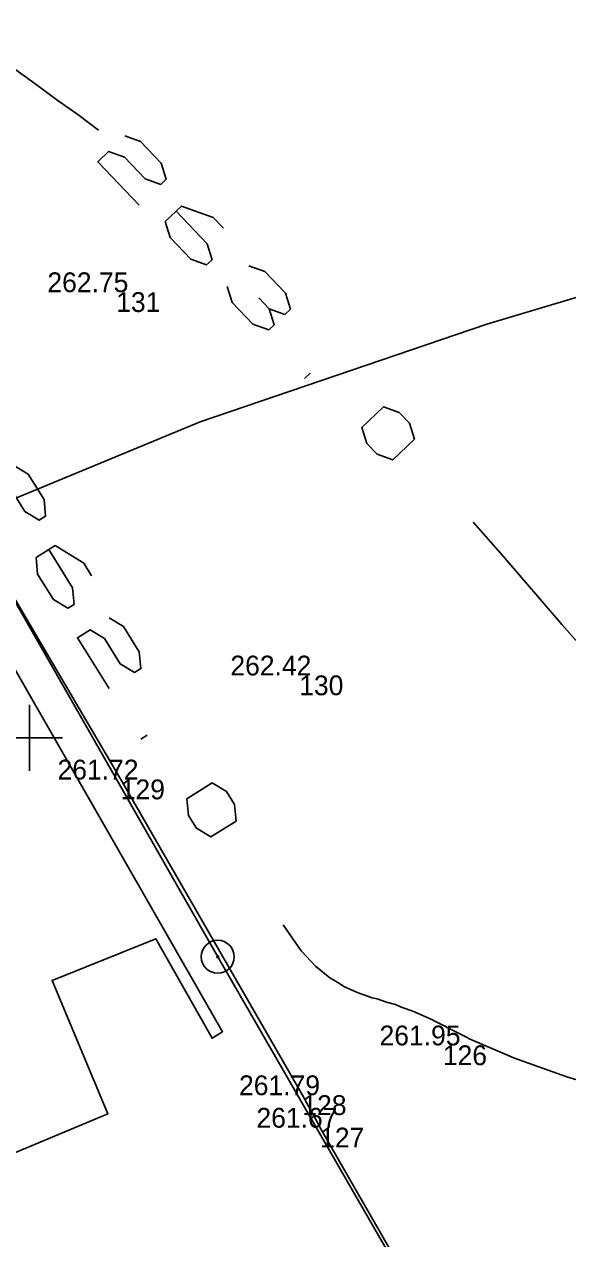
# Model space of a CAD drawing. Extents: x -771260 to -770828, y -1053564 to -1052811.
# Drawn here: x -771150.16 to -771133.69, y -1053315.19 to -1053278.38 of the extents above; entities that cross this region are included whole.
import ezdxf

# ---------------------------------------------------------------- set-up
doc = ezdxf.new("R2010")
doc.units = 0
for name, color, linetype in [('14_8_2023_krizky', 7, 'Continuous'), ('25_3_2019_krizky_JTSK', 7, 'Continuous'), ('25_3_2019_oploceni', 7, 'Continuous'), ('25_3_2019_vrstevnice_interval_po_1m', 7, 'Continuous'), ('25_3_2019_vstup_vjezd_pozemek', 7, 'Continuous'), ('25_3_2019_zamereny_bod', 7, 'Continuous'), ('25_3_2019_zamereny_bod_cislo', 7, 'Continuous'), ('25_3_2019_zamereny_bod_vyska', 7, 'Continuous'), ('Default', 7, 'Continuous'), ('DKM_Hranice parcel', 7, 'Continuous'), ('DKM_Značky bodu BP', 7, 'Continuous')]:
    doc.layers.add(name, color=color, linetype=linetype)

# ---------------------------------------------------------------- blocks, each defined once
blk = doc.blocks.new('POINT_DISPLAY')
at = {"layer": 'Default'}
blk.add_line((0, 0), (0, 0), dxfattribs=at)
blk = doc.blocks.new('KRIZEK')
at = {"layer": '25_3_2019_krizky_JTSK'}
for p, q in [((0, 10), (0, -10)), ((-10, 0), (10, 0))]:
    blk.add_line(p, q, dxfattribs=at)

msp = doc.modelspace()

# ---------------------------------------------------------------- linework, layer by layer
at = {"layer": '25_3_2019_oploceni'}
for p, q in [((-771147.237, -1053301.266), (-771151.821, -1053293.463)), ((-771141.735, -1053310.835), (-771147.238, -1053301.267)), ((-771134.779, -1053322.964), (-771141.196, -1053311.82))]:
    msp.add_line(p, q, dxfattribs=at)
at = {"layer": '25_3_2019_vrstevnice_interval_po_1m'}
for points in [[(-771153.199, -1053277.504), (-771152.035, -1053278.507), (-771151.999, -1053278.538), (-771151.054, -1053279.264), (-771150.533, -1053279.674), (-771149.799, -1053280.202), (-771149.134, -1053280.696), (-771148.539, -1053281.114), (-771147.912, -1053281.584)], [(-771149.799, -1053280.202), (-771149.799, -1053280.202)], [(-771149.134, -1053280.696), (-771149.134, -1053280.696)], [(-771148.539, -1053281.114), (-771148.539, -1053281.114)], [(-771147.114, -1053281.763), (-771146.636, -1053281.934), (-771146.009, -1053282.591), (-771145.86, -1053283.076), (-771146.024, -1053283.232), (-771146.501, -1053283.061), (-771147.128, -1053282.404), (-771147.606, -1053282.233), (-771147.934, -1053282.546), (-771146.68, -1053283.859)], [(-771145.561, -1053284.046), (-771144.621, -1053285.03), (-771144.471, -1053285.515), (-771144.636, -1053285.672), (-771145.113, -1053285.501), (-771145.74, -1053284.844), (-771145.889, -1053284.359), (-771145.397, -1053283.889), (-771144.442, -1053284.232), (-771144.128, -1053284.56)], [(-771143.352, -1053285.702), (-771142.875, -1053285.873), (-771142.248, -1053286.53), (-771142.098, -1053287.015), (-771142.263, -1053287.171), (-771142.74, -1053287)], [(-771142.74, -1053287), (-771142.591, -1053287.485), (-771142.755, -1053287.642), (-771143.232, -1053287.47), (-771143.859, -1053286.814), (-771144.009, -1053286.329)], [(-771142.74, -1053287), (-771143.054, -1053286.672)], [(-771141.665, -1053289.111), (-771141.501, -1053288.955)], [(-771139.785, -1053291.081), (-771139.934, -1053290.596), (-771139.277, -1053289.969), (-771138.8, -1053290.14), (-771138.486, -1053290.469), (-771138.337, -1053290.954), (-771138.994, -1053291.581), (-771139.471, -1053291.409), (-771139.785, -1053291.081)], [(-771150.477, -1053291.749), (-771150.044, -1053292.013), (-771149.563, -1053292.783), (-771149.515, -1053293.288), (-771149.708, -1053293.408), (-771150.141, -1053293.144), (-771150.622, -1053292.374), (-771151.055, -1053292.109), (-771151.44, -1053292.35), (-771150.477, -1053293.89)], [(-771136.561, -1053293.471), (-771136.561, -1053293.471)], [(-771136.561, -1053293.471), (-771136.552, -1053293.481), (-771135.648, -1053294.495), (-771133.861, -1053296.577), (-771133.233, -1053297.289)], [(-771149.419, -1053294.298), (-771148.697, -1053295.453), (-771148.649, -1053295.958), (-771148.842, -1053296.079), (-771149.275, -1053295.814), (-771149.756, -1053295.044), (-771149.804, -1053294.539), (-771149.227, -1053294.178), (-771148.361, -1053294.707), (-771148.12, -1053295.092)], [(-771135.648, -1053294.495), (-771135.648, -1053294.495)], [(-771147.591, -1053296.367), (-771147.158, -1053296.632), (-771146.677, -1053297.402), (-771146.629, -1053297.907), (-771146.821, -1053298.027), (-771147.254, -1053297.762), (-771147.735, -1053296.993), (-771148.168, -1053296.728), (-771148.553, -1053296.969), (-771147.591, -1053298.508)], [(-771133.861, -1053296.577), (-771133.861, -1053296.577)], [(-771146.629, -1053300.048), (-771146.436, -1053299.927)], [(-771145.186, -1053302.357), (-771145.234, -1053301.852), (-771144.464, -1053301.371), (-771144.031, -1053301.635), (-771143.79, -1053302.02), (-771143.742, -1053302.525), (-771144.512, -1053303.006), (-771144.945, -1053302.742), (-771145.186, -1053302.357)], [(-771142.312, -1053305.671), (-771142.312, -1053305.671)], [(-771142.312, -1053305.671), (-771141.768, -1053306.462), (-771141.762, -1053306.47), (-771141.332, -1053306.92), (-771140.903, -1053307.276), (-771140.614, -1053307.449), (-771140.474, -1053307.543), (-771140.046, -1053307.736), (-771139.618, -1053307.883), (-771139.466, -1053307.912), (-771139.19, -1053308.014), (-771138.915, -1053308.083), (-771138.762, -1053308.153), (-771138.334, -1053308.313), (-771137.774, -1053308.562), (-771137.758, -1053308.569), (-771136.965, -1053308.977), (-771136.725, -1053309.101), (-771136.697, -1053309.113), (-771135.303, -1053309.712), (-771133.721, -1053310.279), (-771133.087, -1053310.474)], [(-771141.762, -1053306.47), (-771141.762, -1053306.47)], [(-771141.332, -1053306.92), (-771141.332, -1053306.92)], [(-771140.903, -1053307.276), (-771140.903, -1053307.276)], [(-771140.614, -1053307.449), (-771140.614, -1053307.449)], [(-771140.474, -1053307.543), (-771140.474, -1053307.543)], [(-771140.046, -1053307.736), (-771140.046, -1053307.736)], [(-771139.618, -1053307.883), (-771139.618, -1053307.883)], [(-771139.466, -1053307.912), (-771139.466, -1053307.912)], [(-771139.19, -1053308.014), (-771139.19, -1053308.014)], [(-771138.915, -1053308.083), (-771138.915, -1053308.083)], [(-771138.762, -1053308.153), (-771138.762, -1053308.153)], [(-771138.334, -1053308.313), (-771138.334, -1053308.313)], [(-771137.758, -1053308.569), (-771137.758, -1053308.569)], [(-771136.725, -1053309.101), (-771136.725, -1053309.101)], [(-771135.303, -1053309.712), (-771135.303, -1053309.712)], [(-771133.721, -1053310.279), (-771133.721, -1053310.279)]]:
    msp.add_lwpolyline(points, dxfattribs=at)
at = {"layer": '25_3_2019_vstup_vjezd_pozemek'}
msp.add_line((-771141.734, -1053310.835), (-771141.196, -1053311.819), dxfattribs=at)
at = {"layer": 'DKM_Hranice parcel'}
for points in [[(-771151.89, -1053293.35), (-771144.83, -1053290.43), (-771136.15, -1053287.47), (-771127.19, -1053284.79), (-771125.28, -1053284.32)], [(-771134.86, -1053323.01), (-771144.3, -1053306.64), (-771151.89, -1053293.35)], [(-771154.06, -1053298.56), (-771153.54, -1053299.72), (-771150.56, -1053298.42), (-771151.17, -1053297.4), (-771150.85, -1053297.22), (-771144.15, -1053308.91), (-771144.47, -1053309.11), (-771146.17, -1053306.1), (-771149.32, -1053307.36), (-771147.63, -1053311.4), (-771152.05, -1053313.25), (-771152.83, -1053311.43), (-771157.76, -1053313.5), (-771160.11, -1053307.96), (-771160.78, -1053308.25), (-771163.6, -1053301.6), (-771157.66, -1053299.1), (-771157.32, -1053300.01), (-771154.06, -1053298.56)]]:
    msp.add_lwpolyline(points, dxfattribs=at)
at = {"layer": 'DKM_Značky bodu BP'}
for radius in [0.5, 0.0303]:
    msp.add_circle((-771144.3, -1053306.64), radius, dxfattribs=at)

# ---------------------------------------------------------------- block references
at = {"layer": '14_8_2023_krizky', "xscale": 0.1, "yscale": 0.10000000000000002}
msp.add_blockref('KRIZEK', (-771150, -1053300), dxfattribs=at)
at = {"layer": '25_3_2019_zamereny_bod', "xscale": 0.1, "yscale": 0.10000000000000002}
for p in [(-771147.375, -1053286.497), (-771141.83, -1053298.113), (-771147.238, -1053301.267), (-771137.478, -1053309.325), (-771141.735, -1053310.835), (-771141.196, -1053311.82)]:
    msp.add_blockref('POINT_DISPLAY', p, dxfattribs=at)

# ---------------------------------------------------------------- texts
at = {"layer": '25_3_2019_zamereny_bod_cislo'}
for s, p in [('131', (-771147.375, -1053287.097)), ('130', (-771141.83, -1053298.713)), ('129', (-771147.238, -1053301.867)), ('126', (-771137.478, -1053309.925)), ('128', (-771141.735, -1053311.435)), ('127', (-771141.196, -1053312.42))]:
    msp.add_text(s, height=0.6, dxfattribs=at).set_placement(p)
at = {"layer": '25_3_2019_zamereny_bod_vyska'}
for s, p in [('262.75 ', (-771149.461, -1053286.497)), ('262.42 ', (-771143.916, -1053298.113)), ('261.72 ', (-771149.153, -1053301.267)), ('261.95 ', (-771139.396, -1053309.325)), ('261.79 ', (-771143.654, -1053310.835)), ('261.67 ', (-771143.126, -1053311.82))]:
    msp.add_text(s, height=0.6, dxfattribs=at).set_placement(p)

doc.saveas('drawing.dxf')
